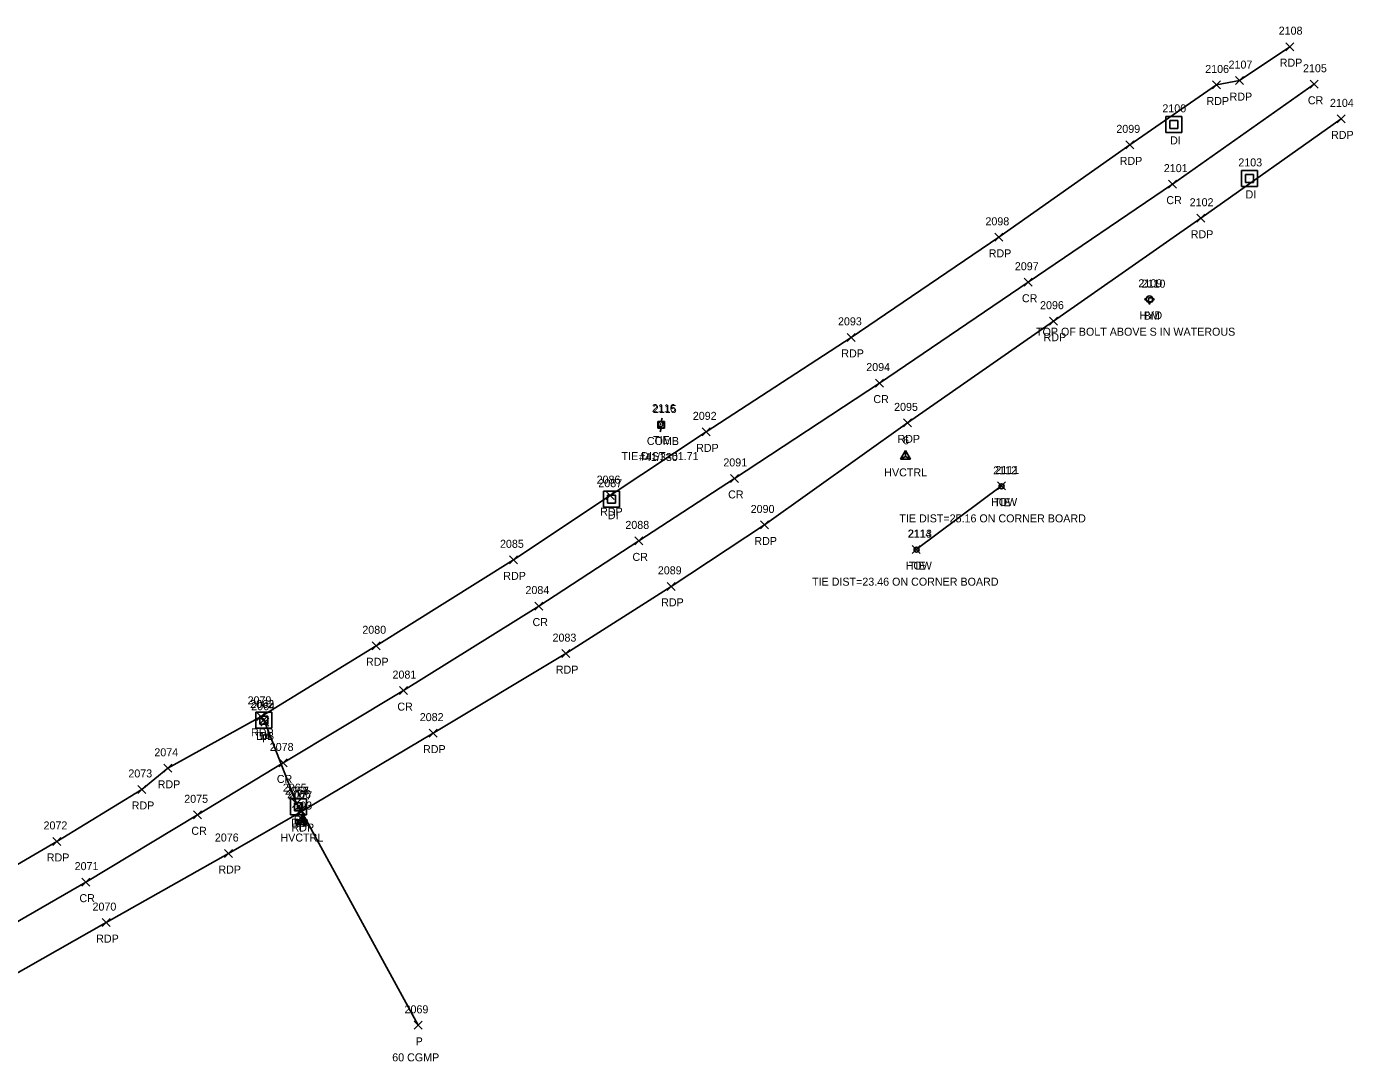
# Model space of a CAD drawing. Extents: x 1657482 to 1661439, y 647981 to 649041.
# Drawn here: x 1660173.9 to 1660505.5, y 648203.9 to 648462.4 of the extents above; entities that cross this region are included whole.
import ezdxf

# ---------------------------------------------------------------- set-up
doc = ezdxf.new("R2010")
doc.units = 0
for name, color, linetype in [('C_A', 7, 'Continuous'), ('C_C', 7, 'Continuous'), ('C_I', 7, 'Continuous'), ('CBP', 7, 'Continuous'), ('CPBM', 7, 'Continuous'), ('CPSM', 7, 'Continuous'), ('D_A', 7, 'Continuous'), ('D_C', 7, 'Continuous'), ('D_I', 7, 'Continuous'), ('D_TIC', 7, 'Continuous'), ('DCP', 7, 'Continuous'), ('DS', 7, 'Continuous'), ('L_A', 7, 'Continuous'), ('L_I', 7, 'Continuous'), ('L_TIC', 7, 'Continuous'), ('LBC', 7, 'Continuous'), ('P_A', 7, 'Continuous'), ('P_I', 7, 'Continuous'), ('P_TIC', 7, 'Continuous'), ('PET', 7, 'Continuous'), ('PRC', 7, 'Continuous'), ('U_A', 7, 'Continuous'), ('U_C', 7, 'Continuous'), ('U_I', 7, 'Continuous'), ('UP', 7, 'Continuous'), ('UWFH', 7, 'Continuous')]:
    doc.layers.add(name, color=color, linetype=linetype)

msp = doc.modelspace()

# ---------------------------------------------------------------- linework, layer by layer
at = {"layer": 'CBP'}
for centre, radius in [((1660332.36, 648363.09), 0.625), ((1660332.36, 648363.09), 0.0833), ((1660417.56, 648347.54), 0.625), ((1660417.56, 648347.54), 0.0833), ((1660396.31, 648331.72), 0.625), ((1660396.31, 648331.72), 0.0833)]:
    msp.add_circle(centre, radius, dxfattribs=at)
at = {"layer": 'CPBM'}
for p, q in [((1660454.23, 648393.66), (1660454.23, 648394.66)), ((1660454.23, 648394.66), (1660455.23, 648394.66)), ((1660455.23, 648393.66), (1660454.23, 648393.66)), ((1660454.73, 648394.17), (1660454.73, 648394.17)), ((1660454.73, 648394.17), (1660454.73, 648394.17)), ((1660455.23, 648394.66), (1660455.23, 648393.66))]:
    msp.add_line(p, q, dxfattribs=at)
at = {"layer": 'CPSM'}
for p, q in [((1660392.29, 648354.3), (1660393.54, 648356.47)), ((1660392.29, 648354.3), (1660393.54, 648355.03)), ((1660392.29, 648354.3), (1660394.79, 648354.3)), ((1660394.79, 648354.3), (1660393.54, 648356.47)), ((1660393.54, 648355.03), (1660393.54, 648356.47)), ((1660393.54, 648355.03), (1660393.54, 648355.03)), ((1660393.54, 648355.03), (1660394.79, 648354.3)), ((1660241.41, 648263.08), (1660242.66, 648265.24)), ((1660243.91, 648263.08), (1660242.66, 648265.24)), ((1660242.66, 648263.8), (1660242.66, 648265.24)), ((1660241.41, 648263.08), (1660242.66, 648263.8)), ((1660241.41, 648263.08), (1660243.91, 648263.08)), ((1660242.66, 648263.8), (1660242.66, 648263.8)), ((1660242.66, 648263.8), (1660243.91, 648263.08))]:
    msp.add_line(p, q, dxfattribs=at)
at = {"layer": 'D_TIC'}
for points in [[(1660232.21, 648288.19), (1660234.21, 648290.19)], [(1660234.21, 648288.19), (1660232.21, 648290.19)], [(1660232.43, 648287.61), (1660234.43, 648289.61)], [(1660234.43, 648287.61), (1660232.43, 648289.61)], [(1660240.34, 648267.27), (1660242.34, 648269.27)], [(1660242.34, 648267.27), (1660240.34, 648269.27)], [(1660240.89, 648266.52), (1660242.89, 648268.52)], [(1660242.89, 648266.52), (1660240.89, 648268.52)], [(1660241.47, 648265.62), (1660243.47, 648267.62)], [(1660243.47, 648265.62), (1660241.47, 648267.62)], [(1660270.76, 648211.89), (1660272.76, 648213.89)], [(1660272.76, 648211.89), (1660270.76, 648213.89)]]:
    msp.add_lwpolyline(points, dxfattribs=at)
at = {"layer": 'DCP'}
for points in [[(1660233.43, 648288.61), (1660241.34, 648268.27)], [(1660242.47, 648266.62), (1660271.76, 648212.89)]]:
    msp.add_lwpolyline(points, dxfattribs=at)
at = {"layer": 'DS'}
for p, q in [((1660458.59, 648439.97), (1660462.59, 648439.97)), ((1660458.59, 648435.97), (1660458.59, 648439.97)), ((1660462.59, 648439.97), (1660462.59, 648435.97)), ((1660459.59, 648436.97), (1660459.59, 648438.97)), ((1660459.59, 648438.97), (1660461.59, 648438.97)), ((1660461.59, 648436.97), (1660459.59, 648436.97)), ((1660460.59, 648437.97), (1660460.59, 648437.97)), ((1660460.59, 648437.97), (1660460.59, 648437.97)), ((1660461.59, 648438.97), (1660461.59, 648436.97)), ((1660462.59, 648435.97), (1660458.59, 648435.97)), ((1660477.46, 648426.47), (1660481.46, 648426.47)), ((1660477.46, 648422.47), (1660477.46, 648426.47)), ((1660478.46, 648423.47), (1660478.46, 648425.47)), ((1660478.46, 648425.47), (1660480.46, 648425.47)), ((1660480.46, 648423.47), (1660478.46, 648423.47)), ((1660479.47, 648424.47), (1660479.47, 648424.47)), ((1660479.47, 648424.47), (1660479.47, 648424.47)), ((1660480.46, 648425.47), (1660480.46, 648423.47)), ((1660481.46, 648426.47), (1660481.46, 648422.47)), ((1660481.46, 648422.47), (1660477.46, 648422.47)), ((1660318.11, 648346.33), (1660322.11, 648346.33)), ((1660318.11, 648342.33), (1660318.11, 648346.33)), ((1660319.11, 648343.33), (1660319.11, 648345.33)), ((1660319.11, 648345.33), (1660321.11, 648345.33)), ((1660320.12, 648344.33), (1660320.12, 648344.33)), ((1660320.12, 648344.33), (1660320.12, 648344.33)), ((1660321.11, 648345.33), (1660321.11, 648343.33)), ((1660322.11, 648346.33), (1660322.11, 648342.33)), ((1660322.11, 648342.33), (1660318.11, 648342.33)), ((1660321.11, 648343.33), (1660319.11, 648343.33)), ((1660231.16, 648291.15), (1660235.16, 648291.15)), ((1660231.16, 648287.15), (1660231.16, 648291.15)), ((1660235.16, 648291.15), (1660235.16, 648287.15)), ((1660232.16, 648288.15), (1660232.16, 648290.15)), ((1660232.16, 648290.15), (1660234.16, 648290.15)), ((1660234.16, 648288.15), (1660232.16, 648288.15)), ((1660233.16, 648289.15), (1660233.16, 648289.15)), ((1660233.16, 648289.15), (1660233.16, 648289.15)), ((1660234.16, 648290.15), (1660234.16, 648288.15)), ((1660235.16, 648287.15), (1660231.16, 648287.15)), ((1660239.84, 648269.48), (1660243.84, 648269.48)), ((1660239.84, 648265.48), (1660239.84, 648269.48)), ((1660240.84, 648266.48), (1660240.84, 648268.48)), ((1660240.84, 648268.48), (1660242.84, 648268.48)), ((1660241.84, 648267.48), (1660241.84, 648267.48)), ((1660241.84, 648267.48), (1660241.84, 648267.48)), ((1660242.84, 648268.48), (1660242.84, 648266.48)), ((1660243.84, 648269.48), (1660243.84, 648265.48)), ((1660243.84, 648265.48), (1660239.84, 648265.48)), ((1660242.84, 648266.48), (1660240.84, 648266.48))]:
    msp.add_line(p, q, dxfattribs=at)
at = {"layer": 'L_TIC'}
for points in [[(1660416.52, 648346.63), (1660418.52, 648348.63)], [(1660418.52, 648346.63), (1660416.52, 648348.63)], [(1660395.2, 648330.74), (1660397.2, 648332.74)], [(1660397.2, 648330.74), (1660395.2, 648332.74)]]:
    msp.add_lwpolyline(points, dxfattribs=at)
at = {"layer": 'LBC'}
msp.add_lwpolyline([(1660417.52, 648347.63), (1660396.2, 648331.74)], dxfattribs=at)
at = {"layer": 'P_TIC'}
for points in [[(1660488.57, 648456.38), (1660490.57, 648458.38)], [(1660490.57, 648456.38), (1660488.57, 648458.38)], [(1660476.03, 648447.9), (1660478.03, 648449.9)], [(1660478.03, 648447.9), (1660476.03, 648449.9)], [(1660470.26, 648446.81), (1660472.26, 648448.81)], [(1660472.26, 648446.81), (1660470.26, 648448.81)], [(1660494.64, 648446.99), (1660496.64, 648448.99)], [(1660496.64, 648446.99), (1660494.64, 648448.99)], [(1660501.37, 648438.34), (1660503.37, 648440.34)], [(1660503.37, 648438.34), (1660501.37, 648440.34)], [(1660448.56, 648431.85), (1660450.56, 648433.85)], [(1660450.56, 648431.85), (1660448.56, 648433.85)], [(1660459.29, 648422.04), (1660461.29, 648424.04)], [(1660461.29, 648422.04), (1660459.29, 648424.04)], [(1660466.33, 648413.52), (1660468.33, 648415.52)], [(1660468.33, 648413.52), (1660466.33, 648415.52)], [(1660415.85, 648408.75), (1660417.85, 648410.75)], [(1660417.85, 648408.75), (1660415.85, 648410.75)], [(1660423.19, 648397.53), (1660425.19, 648399.53)], [(1660425.19, 648397.53), (1660423.19, 648399.53)], [(1660429.56, 648387.8), (1660431.56, 648389.8)], [(1660431.56, 648387.8), (1660429.56, 648389.8)], [(1660379, 648383.76), (1660381, 648385.76)], [(1660381, 648383.76), (1660379, 648385.76)], [(1660386.07, 648372.34), (1660388.07, 648374.34)], [(1660388.07, 648372.34), (1660386.07, 648374.34)], [(1660393.03, 648362.39), (1660395.03, 648364.39)], [(1660395.03, 648362.39), (1660393.03, 648364.39)], [(1660342.73, 648360.15), (1660344.73, 648362.15)], [(1660344.73, 648360.15), (1660342.73, 648362.15)], [(1660349.79, 648348.52), (1660351.79, 648350.52)], [(1660351.79, 648348.52), (1660349.79, 648350.52)], [(1660318.74, 648344.22), (1660320.74, 648346.22)], [(1660320.74, 648344.22), (1660318.74, 648346.22)], [(1660357.28, 648336.89), (1660359.28, 648338.89)], [(1660359.28, 648336.89), (1660357.28, 648338.89)], [(1660325.88, 648332.91), (1660327.88, 648334.91)], [(1660327.88, 648332.91), (1660325.88, 648334.91)], [(1660294.55, 648328.18), (1660296.55, 648330.18)], [(1660296.55, 648328.18), (1660294.55, 648330.18)], [(1660334, 648321.56), (1660336, 648323.56)], [(1660336, 648321.56), (1660334, 648323.56)], [(1660300.91, 648316.63), (1660302.91, 648318.63)], [(1660302.91, 648316.63), (1660300.91, 648318.63)], [(1660260.23, 648306.71), (1660262.23, 648308.71)], [(1660262.23, 648306.71), (1660260.23, 648308.71)], [(1660307.67, 648304.75), (1660309.67, 648306.75)], [(1660309.67, 648304.75), (1660307.67, 648306.75)], [(1660267.12, 648295.51), (1660269.12, 648297.51)], [(1660269.12, 648295.51), (1660267.12, 648297.51)], [(1660231.49, 648289.08), (1660233.49, 648291.08)], [(1660233.49, 648289.08), (1660231.49, 648291.08)], [(1660274.5, 648284.89), (1660276.5, 648286.89)], [(1660276.5, 648284.89), (1660274.5, 648286.89)], [(1660208.18, 648276.1), (1660210.18, 648278.1)], [(1660210.18, 648276.1), (1660208.18, 648278.1)], [(1660237.02, 648277.44), (1660239.02, 648279.44)], [(1660239.02, 648277.44), (1660237.02, 648279.44)], [(1660201.69, 648270.82), (1660203.69, 648272.82)], [(1660203.69, 648270.82), (1660201.69, 648272.82)], [(1660215.65, 648264.48), (1660217.65, 648266.48)], [(1660217.65, 648264.48), (1660215.65, 648266.48)], [(1660241.63, 648265.31), (1660243.63, 648267.31)], [(1660243.63, 648265.31), (1660241.63, 648267.31)], [(1660180.49, 648257.83), (1660182.49, 648259.83)], [(1660182.49, 648257.83), (1660180.49, 648259.83)], [(1660223.35, 648254.81), (1660225.35, 648256.81)], [(1660225.35, 648254.81), (1660223.35, 648256.81)], [(1660187.69, 648247.66), (1660189.69, 648249.66)], [(1660189.69, 648247.66), (1660187.69, 648249.66)], [(1660192.82, 648237.55), (1660194.82, 648239.55)], [(1660194.82, 648237.55), (1660192.82, 648239.55)]]:
    msp.add_lwpolyline(points, dxfattribs=at)
at = {"layer": 'PET'}
for points in [[(1660147.04, 648238.71), (1660181.49, 648258.83), (1660202.69, 648271.82), (1660209.18, 648277.1), (1660232.49, 648290.08), (1660261.23, 648307.71), (1660295.55, 648329.18), (1660319.74, 648345.22), (1660343.73, 648361.15), (1660380, 648384.76), (1660416.85, 648409.75), (1660449.56, 648432.85), (1660471.26, 648447.81), (1660477.03, 648448.9), (1660489.57, 648457.38)], [(1660157.8, 648218.16), (1660193.82, 648238.55), (1660224.35, 648255.81), (1660242.63, 648266.31), (1660275.5, 648285.89), (1660308.67, 648305.75), (1660335, 648322.56), (1660358.28, 648337.89), (1660394.03, 648363.39), (1660430.56, 648388.8), (1660467.33, 648414.52), (1660502.37, 648439.34)]]:
    msp.add_lwpolyline(points, dxfattribs=at)
at = {"layer": 'PRC'}
msp.add_lwpolyline([(1660151.73, 648227.3), (1660188.69, 648248.66), (1660216.65, 648265.48), (1660238.02, 648278.44), (1660268.12, 648296.51), (1660301.91, 648317.63), (1660326.88, 648333.91), (1660350.79, 648349.52), (1660387.07, 648373.34), (1660424.19, 648398.53), (1660460.29, 648423.04), (1660495.64, 648447.99)], dxfattribs=at)
at = {"layer": 'UP'}
for p, q in [((1660331.69, 648362.04), (1660331.69, 648363.7)), ((1660331.69, 648363.7), (1660333.35, 648363.7)), ((1660332.77, 648364.54), (1660332.52, 648363.7)), ((1660333.35, 648363.7), (1660333.35, 648362.04)), ((1660333.35, 648362.04), (1660331.69, 648362.04)), ((1660332.27, 648361.2), (1660332.52, 648362.04)), ((1660332.52, 648362.87), (1660332.52, 648362.87))]:
    msp.add_line(p, q, dxfattribs=at)
msp.add_circle((1660332.52, 648362.87), 0.833, dxfattribs=at)
at = {"layer": 'UWFH'}
msp.add_line((1660454.51, 648394.28), (1660454.51, 648394.28), dxfattribs=at)
for centre, radius in [((1660453.51, 648394.28), 0.167), ((1660454.51, 648394.28), 0.833), ((1660454.51, 648393.28), 0.167), ((1660455.51, 648394.28), 0.167)]:
    msp.add_circle(centre, radius, dxfattribs=at)

# ---------------------------------------------------------------- texts
at = {"layer": 'C_A'}
for s, p in [('BM', (1660453.05, 648389.17)), ('TIE', (1660330.44, 648358.09)), ('HVCTRL', (1660388.23, 648350.03)), ('TIE', (1660415.64, 648342.54)), ('TIE', (1660394.39, 648326.72)), ('HVCTRL', (1660237.35, 648258.8))]:
    msp.add_text(s, height=2, dxfattribs=at).set_placement(p)
at = {"layer": 'C_C'}
for s, p in [('TOP OF BOLT ABOVE S IN WATEROUS', (1660426.15, 648385.17)), ('TIE DIST=61.71', (1660322.58, 648354.09)), ('TIE DIST=25.16 ON CORNER BOARD', (1660392.01, 648338.54)), ('TIE DIST=23.46 ON CORNER BOARD', (1660370.19, 648322.72))]:
    msp.add_text(s, height=2, dxfattribs=at).set_placement(p)
at = {"layer": 'C_I'}
for s, p in [('2110', (1660452.52, 648397.17)), ('2116', (1660330.18, 648366.09)), ('6', (1660392.92, 648358.03)), ('2112', (1660415.44, 648350.54)), ('2113', (1660394.19, 648334.72)), ('103', (1660240.79, 648266.8))]:
    msp.add_text(s, height=2, dxfattribs=at).set_placement(p)
at = {"layer": 'D_A'}
for s, p in [('DI', (1660459.65, 648432.97)), ('DI', (1660478.52, 648419.47)), ('DI', (1660319.17, 648339.33)), ('DIB', (1660231.31, 648284.19)), ('DI', (1660232.22, 648284.15)), ('P', (1660232.81, 648283.61)), ('DIB', (1660240, 648262.52)), ('P', (1660240.72, 648263.27)), ('DI', (1660240.9, 648262.48)), ('P', (1660241.85, 648261.62)), ('P', (1660271.13, 648207.89))]:
    msp.add_text(s, height=2, dxfattribs=at).set_placement(p)
at = {"layer": 'D_C'}
msp.add_text('60 CGMP', height=2, dxfattribs=at).set_placement((1660265.28, 648203.89))
at = {"layer": 'D_I'}
for s, p in [('2100', (1660457.73, 648440.97)), ('2103', (1660476.7, 648427.47)), ('2087', (1660316.78, 648347.33)), ('2062', (1660229.78, 648292.15)), ('2063', (1660229.82, 648292.19)), ('2064', (1660230.04, 648291.61)), ('2065', (1660237.95, 648271.27)), ('2068', (1660238.46, 648270.48)), ('2067', (1660238.51, 648270.52)), ('2066', (1660239.03, 648269.62)), ('2069', (1660268.36, 648215.89))]:
    msp.add_text(s, height=2, dxfattribs=at).set_placement(p)
at = {"layer": 'L_A'}
for p in [(1660414.91, 648342.63), (1660393.58, 648326.74)]:
    msp.add_text('HOW', height=2, dxfattribs=at).set_placement(p)
at = {"layer": 'L_I'}
for s, p in [('2111', (1660415.97, 648350.63)), ('2114', (1660394.07, 648334.74))]:
    msp.add_text(s, height=2, dxfattribs=at).set_placement(p)
at = {"layer": 'P_A'}
for s, p in [('RDP', (1660487.05, 648452.38)), ('RDP', (1660468.75, 648442.81)), ('RDP', (1660474.52, 648443.9)), ('CR', (1660494.08, 648442.99)), ('RDP', (1660499.86, 648434.34)), ('RDP', (1660447.05, 648427.85)), ('CR', (1660458.72, 648418.04)), ('RDP', (1660464.81, 648409.52)), ('RDP', (1660414.33, 648404.75)), ('CR', (1660422.63, 648393.53)), ('RDP', (1660428.04, 648383.8)), ('RDP', (1660377.49, 648379.76)), ('CR', (1660385.5, 648368.34)), ('RDP', (1660391.52, 648358.39)), ('RDP', (1660341.22, 648356.15)), ('CR', (1660349.22, 648344.52)), ('RDP', (1660317.23, 648340.22)), ('RDP', (1660355.77, 648332.89)), ('CR', (1660325.31, 648328.91)), ('RDP', (1660293.03, 648324.18)), ('RDP', (1660332.48, 648317.56)), ('CR', (1660300.34, 648312.63)), ('RDP', (1660258.72, 648302.71)), ('RDP', (1660306.16, 648300.75)), ('CR', (1660266.55, 648291.51)), ('RDP', (1660229.98, 648285.08)), ('RDP', (1660272.98, 648280.89)), ('RDP', (1660206.67, 648272.1)), ('CR', (1660236.45, 648273.44)), ('RDP', (1660200.18, 648266.82)), ('CR', (1660215.08, 648260.48)), ('RDP', (1660240.12, 648261.31)), ('RDP', (1660178.97, 648253.83)), ('RDP', (1660221.84, 648250.81)), ('CR', (1660187.12, 648243.66)), ('RDP', (1660191.31, 648233.55))]:
    msp.add_text(s, height=2, dxfattribs=at).set_placement(p)
at = {"layer": 'P_I'}
for s, p in [('2108', (1660486.79, 648460.38)), ('2107', (1660474.26, 648451.9)), ('2106', (1660468.43, 648450.81)), ('2105', (1660492.87, 648450.99)), ('2104', (1660499.6, 648442.34)), ('2099', (1660446.22, 648435.85)), ('2101', (1660458.09, 648426.04)), ('2102', (1660464.55, 648417.52)), ('2098', (1660413.51, 648412.75)), ('2097', (1660420.86, 648401.53)), ('2096', (1660427.16, 648391.8)), ('2093', (1660376.67, 648387.76)), ('2094', (1660383.73, 648376.34)), ('2095', (1660390.69, 648366.39)), ('2092', (1660340.39, 648364.15)), ('2091', (1660348.02, 648352.52)), ('2086', (1660316.35, 648348.22)), ('2090', (1660354.85, 648340.89)), ('2088', (1660323.54, 648336.91)), ('2085', (1660292.21, 648332.18)), ('2089', (1660331.65, 648325.56)), ('2084', (1660298.57, 648320.63)), ('2080', (1660257.81, 648310.71)), ('2083', (1660305.34, 648308.75)), ('2081', (1660265.35, 648299.51)), ('2079', (1660229.14, 648293.08)), ('2082', (1660272.16, 648288.89)), ('2074', (1660205.84, 648280.1)), ('2078', (1660234.68, 648281.44)), ('2073', (1660199.35, 648274.82)), ('2077', (1660239.3, 648269.31)), ('2075', (1660213.31, 648268.48)), ('2072', (1660178.15, 648261.83)), ('2076', (1660220.96, 648258.81)), ('2071', (1660185.92, 648251.66)), ('2070', (1660190.39, 648241.55))]:
    msp.add_text(s, height=2, dxfattribs=at).set_placement(p)
at = {"layer": 'U_A'}
for s, p in [('HYD', (1660452.03, 648389.28)), ('COMB', (1660328.91, 648357.87))]:
    msp.add_text(s, height=2, dxfattribs=at).set_placement(p)
at = {"layer": 'U_C'}
msp.add_text('#41/330', height=2, dxfattribs=at).set_placement((1660326.97, 648353.87))
at = {"layer": 'U_I'}
for s, p in [('2109', (1660451.73, 648397.28)), ('2115', (1660330.4, 648365.87))]:
    msp.add_text(s, height=2, dxfattribs=at).set_placement(p)

doc.saveas('drawing.dxf')
